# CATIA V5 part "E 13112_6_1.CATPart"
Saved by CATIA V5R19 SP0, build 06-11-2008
Part number: E 13112_6_1
Definition: E 13112_6_1
Nomenclature: E 13112_6_1
Source: Unknown
Description: PART--DESC
Bounding box of the stored display mesh (mm): x -4 to 4, y -3.9 to 3.991, z -16 to 0
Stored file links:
  C:\Users\jsmid\Desktop\DP_Smidak_Forma LEGO\E 13112_6_1.CATPart
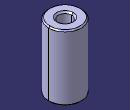
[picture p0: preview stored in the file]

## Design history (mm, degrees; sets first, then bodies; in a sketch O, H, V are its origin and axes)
Body1 "MANIFOLD_SOLID_BREP #136" (main body)
  Solid1: solid without history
